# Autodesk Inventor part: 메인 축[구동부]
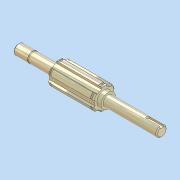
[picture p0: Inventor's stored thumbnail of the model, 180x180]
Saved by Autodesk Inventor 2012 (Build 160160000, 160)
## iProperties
Company: 한국ATC센터
Created: 2012-05
Part Number: 메인 축[구동부]
Document SubType Name: 모델링
Designer: KYOUNG IL JANG
Mass: 168.566 g
Surface Area: 72.5109 cm^2
Volume: 21.4461 cm^3
Density: 7.86 g/cm^3
Material: 강, 연강
변환 표준: STEP AP214IS
파일 이름: C:\Users\SeoGD\Desktop\?쒗뿕\硫붿씤 異?.stp
전처리기: Build: 253, Release: 2010 SP1 - Date: Wed 07/29/2009
전송 단위: 밀리미터
불확실성: 0.01
Author: KYOUNG IL JANG
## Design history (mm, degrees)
sketch "스케치1"
  geometry: L1 (-69.5, 0)-(69.5, 0); L2 (69.5, 0)-(69.5, 5); L3 (69.5, 5)-(55.5, 5); L4 (55.5, 5)-(55.5, 4.8); L5 (55.5, 4.8)-(54.35, 4.8); L6 (54.35, 4.8)-(54.35, 5); L7 (54.35, 5)-(30.5, 5); L8 (30.5, 5)-(30.5, 9); L9 (30.5, 9)-(-13.5, 9); L10 (-13.5, 9)-(-13.5, 7); L11 (-13.5, 7)-(-17.5, 7); L12 (-17.5, 7)-(-17.5, 5); L13 (-17.5, 5)-(-69.5, 5); L14 (-69.5, 5)-(-69.5, 0); 2 further points
  constraints: 28 end point, 9 parallel, 4 collinear, 2 perpendicular, 1 coincident, 1 horizontal, 1 midpoint
  dimensions: "d2" = 1.15 distance between parallel lines of L6 L4; "d3" = 10 diameter of L3 L1; "d4" = 9.6 diameter of L5 L1; "d6" = 44 distance between parallel lines of L10 L8; "d7" = 4 distance between parallel lines of L12 L10; "d8" = 14 diameter of L11 L1; "d9" = 18 diameter of L9 L1; "d33" = 52 distance from line of L12.end L14; "d37" = 39 distance between parallel lines of L8 L2; "d38" = 14 distance between parallel lines of L2 L4
revolve "회전1" sketch "스케치1" stored, may be unused: angle "d10" = 90 deg
sketch "스케치2"
  geometry: L1 (2.5, 10.712)-(2.5, 8.646); L2 (-2.5, 10.712)-(-2.5, 8.646); A1 r 9 centre (0, 0) between (2.5, 8.646) and (-2.5, 8.646) reference; A2 r 11 centre (0, 0) between (2.5, 10.712) and (-2.5, 10.712); 1 further point
  constraints: 4 end point, 4 point on circle, 2 parallel, 1 centre point, 1 coincident, 1 vertical
  dimensions: "d11" = 22 diameter of A2; "d12" = 5 distance between parallel lines of L1 L2
extrude "돌출1" join sketch "스케치2" stored distance "d13" = 10; taper "d14" = 0 deg
chamfer "모따기1" distance "d15" = 1; stored, may be unused: second distance "d16" = 2, angle "d17" = 45 deg
node "작업 평면1"
node "작업 평면2"
sketch "스케치3"
  geometry: L1 (2.5, 10.712)-(2.5, 10.198); L2 (-2.5, 10.712)-(-2.5, 10.198); A1 r 11 centre (0, 0) between (2.5, 10.712) and (-2.5, 10.712) reference; A2 r 10.5 centre (0, 0) between (2.5, 10.198) and (-2.5, 10.198); 1 further point
  constraints: 4 end point, 2 point on circle, 1 centre point, 1 coincident, 1 parallel, 1 vertical
  dimensions: "d19" = 21 diameter of A2
extrude "돌출2" cut sketch "스케치3" distance "d20" = 1.35; taper "d21" = 0 deg
node "작업 평면3"
sketch "스케치4"
  geometry: L1 (-26, -5)-(-26, 5) reference; L2 (-26, 1.5)-(-12.5, 1.5); L3 (-12.5, -1.5)-(-26, -1.5); A1 r 1.5 centre (-12.5, 0) between (-12.5, -1.5) and (-12.5, 1.5); 2 further points
  constraints: 4 end point, 2 perpendicular, 2 point on circle, 2 point on line, 2 tangent, 1 centre point, 1 horizontal alignment, 1 midpoint
  dimensions: "d25" = 3 distance between parallel lines of L3 L2; "d26" = 15 dimension on A1 L1
extrude "돌출3" cut sketch "스케치4" distance "d27" = 1.8; taper "d28" = 0 deg
chamfer "모따기2" distance "d29" = 1; stored, may be unused: second distance "d30" = 2, angle "d31" = 45 deg
node "솔리드1"
node "솔리드 본체"
node "곡면 본체"
mirror "대칭1"
pattern_circular "원형 패턴1" dims "d23" = 360 deg
node "솔리드2"
other parameters: "d18" = -1.65
